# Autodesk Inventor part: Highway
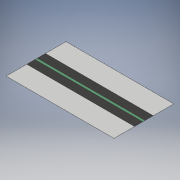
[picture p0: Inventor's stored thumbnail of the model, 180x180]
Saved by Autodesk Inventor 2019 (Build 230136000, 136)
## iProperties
Created: 2018-12
Part Number: Highway
Material: Generic
Document SubType Name: Modeling
Designer: Patel Family
Density: 1 g/cm^3
Appearance: Default
Author: Patel Family
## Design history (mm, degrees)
sketch "Sketch1"
  geometry: L1 (-170.581, 94.659)-(170.581, 94.659); L2 (170.581, 94.659)-(170.581, -94.659); L3 (170.581, -94.659)-(-170.581, -94.659); L4 (-170.581, -94.659)-(-170.581, 94.659); L5 (-170.581, 94.659)-(170.581, -94.659); L6 (170.581, 94.659)-(-170.581, -94.659); 1 further point
  constraints: 12 end point, 2 midpoint, 2 parallel, 1 horizontal, 1 perpendicular
extrude "Extrusion1" new body sketch "Sketch1" distance "d0" = 0.2; taper "d1" = 0 deg
sketch "Sketch2"
  geometry: L1 (170.581, -94.659)-(170.581, 94.659) reference; L2 (-170.581, -4.069)-(170.581, -4.069); L3 (170.581, -4.069)-(170.581, 4.069); L4 (170.581, 4.069)-(-170.581, 4.069); L5 (-170.581, 4.069)-(-170.581, -4.069); L6 (-170.581, -4.069)-(170.581, 4.069); L7 (170.581, -4.069)-(-170.581, 4.069); 1 further point
  constraints: 12 end point, 2 midpoint, 2 parallel, 1 horizontal, 1 perpendicular, 1 point on line
extrude "Extrusion2" join sketch "Sketch2" distance "d2" = 0.0002; taper "d3" = 0 deg
sketch "Sketch3"
  geometry: L1 (-170.581, -29.695)-(170.581, -29.695); L2 (170.581, -29.695)-(170.581, 29.695); L3 (170.581, 29.695)-(-170.581, 29.695); L4 (-170.581, 29.695)-(-170.581, -29.695); L5 (-170.581, -29.695)-(170.581, 29.695); L6 (170.581, -29.695)-(-170.581, 29.695); 1 further point
  constraints: 12 end point, 2 midpoint, 2 parallel, 1 horizontal, 1 perpendicular
extrude "Extrusion3" cut sketch "Sketch3" distance "d4" = 0.0004; taper "d5" = 0 deg
sketch "Sketch4"
  geometry: L1 (170.581, 29.695)-(170.581, -29.695) reference; L2 (-170.581, -3.334)-(170.581, -3.334); L3 (170.581, -3.334)-(170.581, 3.334); L4 (170.581, 3.334)-(-170.581, 3.334); L5 (-170.581, 3.334)-(-170.581, -3.334); L6 (-170.581, -3.334)-(170.581, 3.334); L7 (170.581, -3.334)-(-170.581, 3.334); 1 further point
  constraints: 12 end point, 2 midpoint, 2 parallel, 1 horizontal, 1 perpendicular, 1 point on line
extrude "Extrusion4" join sketch "Sketch4" distance "d6" = 0.0002; taper "d7" = 0 deg
body "Solid1"
